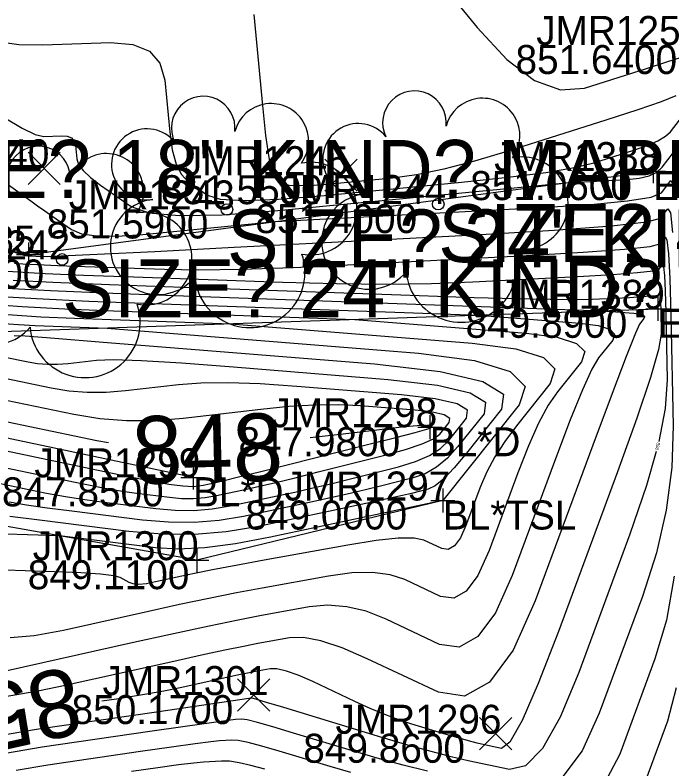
# Model space of a CAD drawing. Extents: x 1654928 to 1810050, y 486881 to 626330.
# Drawn here: x 1801531.06 to 1801558.26, y 489829.65 to 489860.85 of the extents above; entities that cross this region are included whole.
import ezdxf

# ---------------------------------------------------------------- set-up
doc = ezdxf.new("R2010")
doc.units = 0
for name, color, linetype in [('DR_X_Ditch', 7, 'Continuous'), ('DT_X_Contour_Major', 7, 'Continuous'), ('DT_X_Contour_Minor', 7, 'Continuous'), ('SV_X_Random_Point', 7, 'Continuous'), ('SV_X_Shot_Marker', 7, 'Continuous'), ('SV_X_Text_Comment', 7, 'Continuous'), ('SV_X_Text_Elevation', 7, 'Continuous'), ('SV_X_Text_Name', 7, 'Continuous'), ('SV_X_Toe_of_Slope', 7, 'Continuous'), ('SV_X_Top_of_Bank', 7, 'Continuous'), ('VG_X_Cells', 7, 'Continuous'), ('VG_X_Text', 7, 'Continuous')]:
    doc.layers.add(name, color=color, linetype=linetype)

msp = doc.modelspace()

# ---------------------------------------------------------------- linework, layer by layer
at = {"layer": 'DR_X_Ditch'}
msp.add_lwpolyline([(1801538.429, 489841.719), (1801527.515, 489844.014), (1801519.444, 489845.441), (1801503.521, 489842.761), (1801490.506, 489842.113), (1801478.561, 489839.498), (1801468.658, 489833.373), (1801465.597, 489830.762), (1801453.487, 489824.594)], dxfattribs=at)
at = {"layer": 'DT_X_Contour_Major'}
for points in [[(1801530.633, 489856.59), (1801531.351, 489856.161), (1801531.891, 489855.907), (1801532.252, 489855.829), (1801532.978, 489855.853), (1801533.218, 489855.835), (1801533.396, 489855.762), (1801533.51, 489855.634), (1801533.562, 489855.452), (1801533.615, 489854.892), (1801533.691, 489854.667), (1801533.882, 489854.412), (1801534.186, 489854.126), (1801534.603, 489853.809), (1801535.869, 489852.923), (1801536.604, 489852.664), (1801537.86, 489852.549), (1801539.637, 489852.579), (1801541.935, 489852.754), (1801553.874, 489853.908), (1801556.408, 489854.041), (1801556.905, 489854.094), (1801557.311, 489854.197), (1801557.626, 489854.35), (1801557.849, 489854.553), (1801558.322, 489855.161)], [(1801530.982, 489849.881), (1801532.625, 489849.795), (1801534.966, 489849.695), (1801538.003, 489849.583), (1801547.032, 489849.264), (1801550.067, 489849.164), (1801552.4, 489849.101), (1801554.031, 489849.075), (1801554.96, 489849.086), (1801556.503, 489849.167), (1801557.011, 489849.196), (1801557.379, 489849.224), (1801557.607, 489849.249), (1801557.695, 489849.273), (1801557.742, 489849.333), (1801557.758, 489849.306), (1801557.772, 489849.181), (1801557.783, 489848.958), (1801557.792, 489848.636), (1801557.813, 489847.648), (1801557.705, 489847.014), (1801557.367, 489845.853), (1801556.797, 489844.165), (1801555.997, 489841.951), (1801553.556, 489835.343), (1801552.722, 489833.182), (1801552.051, 489831.655), (1801551.542, 489830.76), (1801551.196, 489830.5), (1801550.491, 489830.649), (1801550.194, 489830.718), (1801549.83, 489830.813), (1801549.4, 489830.934), (1801548.904, 489831.082), (1801547.494, 489831.51), (1801546.95, 489831.689), (1801546.374, 489831.904), (1801545.767, 489832.157), (1801545.129, 489832.446), (1801543.387, 489833.265), (1801542.786, 489833.528), (1801542.293, 489833.705), (1801541.906, 489833.794), (1801541.625, 489833.797), (1801541.019, 489833.687), (1801540.749, 489833.635), (1801540.393, 489833.561), (1801539.95, 489833.466), (1801537.898, 489833.009), (1801537.224, 489832.872), (1801536.344, 489832.716), (1801535.257, 489832.541), (1801534.658, 489832.451)], [(1801530.391, 489848.098), (1801531.202, 489848.038), (1801531.898, 489848.003), (1801534.875, 489847.898), (1801547.758, 489846.856), (1801550.089, 489846.554), (1801551.561, 489846.097), (1801552.173, 489845.483), (1801551.927, 489844.714), (1801548.771, 489840.76), (1801541.633, 489839.241), (1801540.188, 489838.969), (1801538.913, 489838.805), (1801537.807, 489838.75), (1801536.871, 489838.802), (1801532.898, 489839.299), (1801529.368, 489839.415)], [(1801534.926, 489843.146), (1801534.445, 489843.224), (1801530.748, 489844.002)], [(1801530.429, 489842.872), (1801534.177, 489842.084), (1801535.434, 489841.822), (1801536.395, 489841.627), (1801537.059, 489841.499), (1801537.426, 489841.438), (1801538.01, 489841.365), (1801538.227, 489841.347), (1801538.438, 489841.345), (1801538.645, 489841.362), (1801538.847, 489841.395), (1801539.379, 489841.509), (1801539.713, 489841.586), (1801540.314, 489841.733), (1801541.183, 489841.949), (1801545.708, 489843.091), (1801546.821, 489843.374), (1801547.62, 489843.581), (1801548.105, 489843.711), (1801548.275, 489843.766), (1801548.311, 489843.81), (1801548.313, 489843.826), (1801548.292, 489843.838), (1801548.249, 489843.848), (1801548.183, 489843.856), (1801547.976, 489843.873), (1801547.71, 489843.855), (1801547.065, 489843.789), (1801546.042, 489843.675), (1801544.641, 489843.512), (1801543.284, 489843.353)]]:
    msp.add_lwpolyline(points, dxfattribs=at)
at = {"layer": 'DT_X_Contour_Minor'}
for points in [[(1801548.311, 489862.632), (1801550.187, 489860.326), (1801551.415, 489859.003), (1801552.567, 489858.145), (1801553.643, 489857.752), (1801554.643, 489857.825), (1801557.207, 489858.638), (1801558.05, 489858.907), (1801558.656, 489859.104), (1801559.025, 489859.229), (1801559.156, 489859.282), (1801559.191, 489859.326), (1801559.206, 489859.16), (1801559.225, 489858.631), (1801559.248, 489857.739), (1801559.276, 489856.483), (1801559.415, 489849.772)], [(1801558.42, 489857.501), (1801557.809, 489857.26), (1801556.841, 489856.926), (1801555.518, 489856.496), (1801551.514, 489855.226), (1801550.086, 489854.798), (1801548.807, 489854.468), (1801547.675, 489854.234), (1801546.691, 489854.097), (1801544.263, 489853.863), (1801543.451, 489853.797), (1801542.833, 489853.776), (1801542.411, 489853.8), (1801542.184, 489853.868), (1801541.839, 489854.109), (1801541.709, 489854.365), (1801541.578, 489854.949), (1801541.447, 489855.864), (1801541.314, 489857.108), (1801540.959, 489860.864)], [(1801530.348, 489859.76), (1801531.219, 489859.631), (1801532.21, 489859.611), (1801535.008, 489859.706), (1801535.936, 489859.636), (1801536.621, 489859.354), (1801537.062, 489858.862), (1801537.26, 489858.158), (1801537.464, 489856), (1801537.569, 489855.266), (1801537.73, 489854.681), (1801537.947, 489854.245), (1801538.221, 489853.959), (1801539.026, 489853.396), (1801539.556, 489853.236), (1801540.541, 489853.181), (1801541.982, 489853.23), (1801543.878, 489853.384), (1801549.542, 489853.931), (1801551.477, 489854.135), (1801553.036, 489854.337), (1801554.219, 489854.537), (1801555.026, 489854.734), (1801556.674, 489855.257), (1801557.233, 489855.452), (1801557.673, 489855.643), (1801557.993, 489855.83), (1801558.195, 489856.014), (1801558.573, 489856.499)], [(1801530.697, 489853.896), (1801531.712, 489853.159), (1801531.998, 489852.954), (1801532.291, 489852.746), (1801532.591, 489852.535), (1801533.399, 489851.97), (1801533.811, 489851.798), (1801534.442, 489851.708), (1801535.29, 489851.7), (1801536.356, 489851.773), (1801541.842, 489852.303), (1801552.822, 489852.878), (1801554.898, 489853.009), (1801556.423, 489853.156), (1801557.397, 489853.318), (1801557.818, 489853.497), (1801558.206, 489853.995), (1801558.341, 489853.775)], [(1801530.815, 489851.116), (1801531.31, 489850.941), (1801531.377, 489850.92), (1801531.428, 489850.907), (1801531.464, 489850.9), (1801531.54, 489850.892), (1801531.585, 489850.888), (1801531.663, 489850.884), (1801531.774, 489850.879), (1801531.919, 489850.874), (1801532.349, 489850.859), (1801532.957, 489850.878), (1801534.457, 489850.948), (1801536.851, 489851.068), (1801540.138, 489851.238), (1801550.094, 489851.759), (1801553.374, 489851.948), (1801555.75, 489852.125), (1801557.221, 489852.289), (1801557.787, 489852.441), (1801558.09, 489852.829), (1801558.195, 489852.658), (1801558.285, 489851.851)], [(1801544.571, 489850.497), (1801545.079, 489850.521), (1801552.23, 489850.895), (1801554.587, 489851.031), (1801556.293, 489851.158), (1801557.35, 489851.276), (1801557.756, 489851.385), (1801557.974, 489851.664), (1801558.05, 489851.541), (1801558.114, 489850.961), (1801558.167, 489849.926), (1801558.208, 489848.435), (1801558.303, 489843.852), (1801558.25, 489842.121), (1801558.022, 489840.367), (1801557.616, 489838.589), (1801557.035, 489836.789), (1801555.249, 489831.955), (1801554.536, 489830.396), (1801553.735, 489829.344)], [(1801530.537, 489850.266), (1801531.183, 489850.216), (1801532.305, 489850.158), (1801533.902, 489850.09), (1801535.975, 489850.013), (1801542.138, 489849.796), (1801544.363, 489849.735), (1801546.419, 489849.716), (1801548.304, 489849.739), (1801550.02, 489849.804), (1801554.366, 489850.031), (1801555.799, 489850.114), (1801556.836, 489850.191), (1801557.478, 489850.262), (1801557.726, 489850.329), (1801557.858, 489850.498), (1801557.904, 489850.423), (1801557.943, 489850.071), (1801557.975, 489849.442), (1801558, 489848.536), (1801558.058, 489845.75), (1801557.978, 489844.567), (1801557.711, 489843.198)], [(1801531.039, 489850.579), (1801531.384, 489850.552), (1801531.984, 489850.521), (1801532.838, 489850.485), (1801533.947, 489850.444), (1801537.243, 489850.327), (1801538.66, 489850.307), (1801540.438, 489850.332), (1801542.578, 489850.404), (1801544.152, 489850.477)], [(1801530.679, 489849.548), (1801532.536, 489849.446), (1801535.105, 489849.333), (1801538.388, 489849.21), (1801555.372, 489848.612), (1801556.675, 489848.506), (1801556.91, 489848.476), (1801557.059, 489848.429), (1801557.121, 489848.367), (1801557.096, 489848.29), (1801556.914, 489848.061), (1801556.742, 489847.684), (1801556.364, 489846.724), (1801555.778, 489845.182), (1801554.986, 489843.057), (1801552.599, 489836.614), (1801551.677, 489834.565), (1801550.701, 489833.25), (1801549.673, 489832.67), (1801548.591, 489832.824), (1801545.635, 489834.213), (1801544.603, 489834.658), (1801543.725, 489834.95), (1801543, 489835.089), (1801542.429, 489835.076), (1801541.109, 489834.837), (1801540.521, 489834.723), (1801539.746, 489834.563), (1801538.783, 489834.356), (1801537.633, 489834.102), (1801534.317, 489833.361), (1801533.134, 489833.105), (1801532.072, 489832.89), (1801531.129, 489832.716), (1801530.308, 489832.584)], [(1801530.25, 489849.221), (1801531.944, 489849.115), (1801534.116, 489849.011), (1801536.766, 489848.909), (1801550.248, 489848.433), (1801554.446, 489848.093), (1801555.205, 489847.995), (1801555.685, 489847.846), (1801555.884, 489847.646), (1801555.804, 489847.396), (1801555.216, 489846.66), (1801554.94, 489846.191), (1801554.55, 489845.339), (1801554.048, 489844.103), (1801553.432, 489842.483), (1801551.642, 489837.651), (1801550.95, 489836.114), (1801550.219, 489835.128), (1801549.447, 489834.692), (1801548.636, 489834.808), (1801546.419, 489835.85), (1801545.596, 489836.175), (1801544.791, 489836.367), (1801544.003, 489836.427), (1801543.232, 489836.355), (1801541.2, 489835.987), (1801540.294, 489835.812), (1801539.099, 489835.565), (1801537.616, 489835.246), (1801535.845, 489834.855), (1801530.737, 489833.714)], [(1801529.821, 489848.893), (1801531.352, 489848.784), (1801533.126, 489848.689), (1801535.143, 489848.607), (1801545.123, 489848.255), (1801552.216, 489847.681), (1801553.5, 489847.515), (1801554.31, 489847.263), (1801554.647, 489846.925), (1801554.512, 489846.502), (1801553.519, 489845.258), (1801553.137, 489844.699), (1801552.736, 489843.954), (1801552.317, 489843.024), (1801551.878, 489841.909), (1801550.685, 489838.687), (1801550.224, 489837.663), (1801549.736, 489837.005), (1801549.222, 489836.715), (1801548.681, 489836.792), (1801547.203, 489837.487), (1801546.589, 489837.691), (1801545.857, 489837.784), (1801545.005, 489837.765), (1801544.035, 489837.634), (1801541.29, 489837.136), (1801540.224, 489836.936), (1801539.086, 489836.709), (1801537.874, 489836.455), (1801536.589, 489836.173), (1801533.066, 489835.386), (1801531.855, 489835.16), (1801530.865, 489835.071)], [(1801530.76, 489848.453), (1801532.136, 489848.367), (1801533.521, 489848.305), (1801539.999, 489848.077), (1801549.987, 489847.268), (1801551.794, 489847.035), (1801552.936, 489846.68), (1801553.41, 489846.204), (1801553.219, 489845.608), (1801551.821, 489843.856), (1801551.334, 489843.206), (1801550.922, 489842.569), (1801550.586, 489841.945), (1801550.325, 489841.334), (1801549.728, 489839.724), (1801549.497, 489839.211), (1801549.253, 489838.883), (1801548.996, 489838.738), (1801548.726, 489838.776), (1801547.987, 489839.123), (1801547.582, 489839.208), (1801546.923, 489839.201), (1801546.008, 489839.103), (1801544.839, 489838.914), (1801541.381, 489838.286), (1801540.195, 489838.069), (1801539.231, 489837.888), (1801538.488, 489837.742), (1801537.967, 489837.633), (1801536.874, 489837.389), (1801536.498, 489837.319), (1801536.191, 489837.291), (1801535.952, 489837.306), (1801535.781, 489837.364), (1801535.417, 489837.574), (1801535.145, 489837.648), (1801534.602, 489837.713), (1801533.787, 489837.768), (1801532.7, 489837.813), (1801529.44, 489837.921)], [(1801531.029, 489847.594), (1801531.476, 489847.568), (1801532.702, 489847.475), (1801534.706, 489847.318), (1801537.488, 489847.094), (1801545.947, 489846.409), (1801548.655, 489846.099), (1801550.433, 489845.683), (1801551.283, 489845.161), (1801551.204, 489844.533), (1801549.754, 489842.717), (1801549.246, 489842.113), (1801548.811, 489841.663), (1801548.448, 489841.368), (1801548.158, 489841.226), (1801547.48, 489841.055), (1801547.1, 489840.965), (1801546.467, 489840.824), (1801545.582, 489840.632), (1801541.076, 489839.671), (1801539.797, 489839.458), (1801538.487, 489839.355), (1801537.146, 489839.362), (1801535.774, 489839.48), (1801532.074, 489839.943), (1801530.839, 489840.099)], [(1801530.582, 489846.709), (1801531.607, 489846.494), (1801531.998, 489846.429), (1801532.404, 489846.398), (1801532.823, 489846.4), (1801533.257, 489846.435), (1801534.432, 489846.573), (1801535.118, 489846.594), (1801536.292, 489846.554), (1801537.957, 489846.452), (1801540.11, 489846.289), (1801546.506, 489845.771), (1801548.553, 489845.537), (1801549.898, 489845.222), (1801550.54, 489844.828), (1801550.48, 489844.353), (1801549.384, 489842.979), (1801548.961, 489842.513), (1801548.513, 489842.143), (1801548.042, 489841.869), (1801547.545, 489841.693), (1801546.19, 489841.35), (1801545.621, 489841.211), (1801544.929, 489841.052), (1801544.115, 489840.871), (1801543.179, 489840.669), (1801540.518, 489840.102), (1801539.509, 489839.934), (1801538.474, 489839.852), (1801537.416, 489839.858), (1801536.333, 489839.951), (1801533.412, 489840.317), (1801532.394, 489840.449), (1801531.53, 489840.572), (1801530.82, 489840.687)], [(1801529.468, 489841.664), (1801531.568, 489841.223), (1801532.358, 489841.065), (1801533.151, 489840.924), (1801533.949, 489840.799), (1801534.75, 489840.69), (1801536.892, 489840.423), (1801537.686, 489840.354), (1801538.462, 489840.35), (1801539.221, 489840.41), (1801539.961, 489840.533), (1801541.912, 489840.949), (1801542.647, 489841.109), (1801543.391, 489841.279), (1801544.141, 489841.457), (1801544.9, 489841.645), (1801546.933, 489842.159), (1801547.635, 489842.371), (1801548.216, 489842.622), (1801548.676, 489842.912), (1801549.015, 489843.241), (1801549.757, 489844.172), (1801549.798, 489844.494), (1801549.363, 489844.761), (1801548.452, 489844.974), (1801547.065, 489845.133), (1801542.732, 489845.483), (1801541.208, 489845.586), (1801539.883, 489845.632), (1801538.759, 489845.621), (1801537.835, 489845.553), (1801535.638, 489845.295), (1801534.827, 489845.229), (1801534.043, 489845.226), (1801533.285, 489845.284), (1801532.553, 489845.404), (1801530.638, 489845.807)], [(1801529.948, 489842.268), (1801532.873, 489841.653), (1801533.896, 489841.444), (1801534.773, 489841.275), (1801535.504, 489841.149), (1801536.088, 489841.064), (1801537.451, 489840.894), (1801537.956, 489840.85), (1801538.45, 489840.848), (1801538.933, 489840.886), (1801539.404, 489840.964), (1801540.646, 489841.229), (1801541.18, 489841.348), (1801541.852, 489841.506), (1801542.662, 489841.703), (1801543.61, 489841.94), (1801546.32, 489842.625), (1801547.228, 489842.872), (1801547.918, 489843.101), (1801548.39, 489843.312), (1801548.645, 489843.504), (1801549.034, 489843.991), (1801549.055, 489844.16), (1801548.827, 489844.3), (1801548.35, 489844.411), (1801547.624, 489844.494), (1801545.354, 489844.678), (1801544.459, 489844.721), (1801543.474, 489844.71), (1801542.401, 489844.648), (1801541.238, 489844.532), (1801538.019, 489844.155), (1801536.831, 489844.059), (1801535.682, 489844.053), (1801534.571, 489844.138), (1801533.499, 489844.314), (1801530.693, 489844.904)], [(1801557.605, 489842.792), (1801557.207, 489841.377), (1801556.516, 489839.37), (1801554.403, 489833.649), (1801553.629, 489831.789), (1801552.893, 489830.499), (1801552.194, 489829.78), (1801551.533, 489829.63), (1801549.82, 489829.992), (1801549.115, 489830.154), (1801548.285, 489830.369), (1801547.329, 489830.637), (1801546.247, 489830.958), (1801542.192, 489832.19), (1801541.471, 489832.407), (1801541.034, 489832.536), (1801540.879, 489832.579), (1801540.843, 489832.577), (1801538.68, 489832.264), (1801537.015, 489832.022), (1801531.947, 489831.284), (1801530.234, 489831)], [(1801558.349, 489837.624), (1801558.026, 489835.802), (1801557.554, 489834.207), (1801556.096, 489830.261), (1801555.442, 489829.003)], [(1801558.436, 489833.014), (1801558.073, 489831.626), (1801556.942, 489828.567)], [(1801548.136, 489829.56), (1801547.136, 489829.805), (1801546.149, 489830.07), (1801545.175, 489830.354), (1801542.596, 489831.137), (1801541.737, 489831.393), (1801541.094, 489831.574), (1801540.667, 489831.681), (1801540.456, 489831.712), (1801540.182, 489831.696), (1801539.883, 489831.66), (1801539.192, 489831.565), (1801538.11, 489831.41), (1801536.636, 489831.197), (1801532.182, 489830.548), (1801530.662, 489830.287), (1801529.441, 489829.989), (1801528.52, 489829.655), (1801527.898, 489829.284)], [(1801544.969, 489829.502), (1801544.104, 489829.749), (1801541.998, 489830.388), (1801541.283, 489830.597), (1801540.717, 489830.742), (1801540.301, 489830.825), (1801540.034, 489830.845), (1801539.521, 489830.814), (1801539.172, 489830.778), (1801538.512, 489830.692), (1801537.54, 489830.557), (1801536.256, 489830.372), (1801532.417, 489829.813), (1801531.106, 489829.587)], [(1801541.4, 489829.64), (1801540.829, 489829.8), (1801540.341, 489829.91), (1801539.935, 489829.969), (1801539.611, 489829.978), (1801538.86, 489829.933), (1801538.462, 489829.896), (1801537.832, 489829.819), (1801536.97, 489829.703), (1801535.877, 489829.547)]]:
    msp.add_lwpolyline(points, dxfattribs=at)
at = {"layer": 'SV_X_Random_Point'}
for p, q in [((1801531.601, 489853.837), (1801532.934, 489855.172)), ((1801531.601, 489855.172), (1801532.934, 489853.837)), ((1801543.886, 489853.554), (1801545.219, 489854.889)), ((1801543.886, 489854.889), (1801545.219, 489853.554)), ((1801540.276, 489832.042), (1801541.609, 489833.377)), ((1801540.276, 489833.377), (1801541.609, 489832.042)), ((1801550.294, 489830.441), (1801551.627, 489831.776)), ((1801550.294, 489831.776), (1801551.627, 489830.441))]:
    msp.add_line(p, q, dxfattribs=at)
at = {"layer": 'SV_X_Shot_Marker'}
for p, q in [((1801557.484, 489854.89), (1801557.484, 489853.89)), ((1801556.984, 489854.39), (1801557.984, 489854.39)), ((1801557.484, 489854.39), (1801557.484, 489854.39)), ((1801531.615, 489851.439), (1801531.615, 489850.439)), ((1801531.115, 489850.939), (1801532.115, 489850.939)), ((1801531.615, 489850.939), (1801531.615, 489850.939)), ((1801557.678, 489849.192), (1801557.678, 489848.192)), ((1801557.178, 489848.692), (1801558.178, 489848.692)), ((1801557.678, 489848.692), (1801557.678, 489848.692)), ((1801548.238, 489844.292), (1801548.238, 489843.292)), ((1801547.738, 489843.792), (1801548.738, 489843.792)), ((1801548.238, 489843.792), (1801548.238, 489843.792)), ((1801538.429, 489842.219), (1801538.429, 489841.219)), ((1801537.929, 489841.719), (1801538.929, 489841.719)), ((1801538.429, 489841.719), (1801538.429, 489841.719)), ((1801548.771, 489841.26), (1801548.771, 489840.26)), ((1801548.271, 489840.76), (1801549.271, 489840.76)), ((1801548.771, 489840.76), (1801548.771, 489840.76)), ((1801538.587, 489838.79), (1801538.587, 489837.79)), ((1801538.087, 489838.29), (1801539.087, 489838.29)), ((1801538.587, 489838.29), (1801538.587, 489838.29))]:
    msp.add_line(p, q, dxfattribs=at)
at = {"layer": 'SV_X_Toe_of_Slope'}
for points in [[(1801453.22, 489833.952), (1801462.62, 489833.764), (1801469.81, 489840.55), (1801480.323, 489844.16), (1801485.248, 489845.996), (1801491.16, 489848.502), (1801498.28, 489846.461), (1801505.556, 489847.392), (1801507.978, 489849.684), (1801520.732, 489849.249), (1801530.519, 489847.747), (1801557.678, 489848.692)], [(1801548.771, 489840.76), (1801538.587, 489838.29), (1801528.242, 489840.124), (1801519.185, 489843.217), (1801514.834, 489840.706), (1801503.746, 489839.863), (1801493.235, 489835.949), (1801481.982, 489831.828), (1801478.469, 489833.99), (1801472.566, 489830.006), (1801464.849, 489824.991), (1801462.27, 489825.427), (1801460.621, 489820.525)]]:
    msp.add_lwpolyline(points, dxfattribs=at)
at = {"layer": 'SV_X_Top_of_Bank'}
msp.add_lwpolyline([(1801452.193, 489836.758), (1801459.513, 489846.009), (1801465.887, 489850.179), (1801473.853, 489849.345), (1801479.986, 489850.885), (1801482.71, 489854.488), (1801486.035, 489852.905), (1801488.583, 489850.107), (1801492.084, 489852.448), (1801498.522, 489852.672), (1801506.396, 489853.841), (1801518.285, 489853.998), (1801520.681, 489853.368), (1801531.615, 489850.939), (1801557.484, 489854.39)], dxfattribs=at)
at = {"layer": 'VG_X_Cells'}
for centre in [(1801539.835, 489852.803), (1801548.581, 489853.025), (1801533.011, 489850.735)]:
    msp.add_circle(centre, 0.24, dxfattribs=at)
for centre, radius, start, end in [((1801547.597, 489856.392), 1.317, 354.0047, 205.9741), ((1801538.851, 489856.171), 1.317, 354.0047, 205.9741), ((1801550.407, 489855.854), 1.553, 323.83, 165.0376), ((1801541.661, 489855.632), 1.553, 323.83, 165.0376), ((1801536.525, 489854.667), 1.471, 39.0625, 279.5412), ((1801545.272, 489854.889), 1.471, 39.0625, 279.5412), ((1801532.027, 489854.102), 1.317, 354.0047, 205.9741), ((1801534.837, 489853.564), 1.553, 323.83, 165.0376), ((1801552.041, 489853.061), 1.915, 259.1453, 101.4596), ((1801543.295, 489852.839), 1.915, 259.1453, 101.4596), ((1801545.728, 489851.476), 1.974, 96.1722, 320.5737), ((1801536.981, 489851.255), 1.974, 96.1722, 320.5737), ((1801536.471, 489850.771), 1.915, 259.1453, 101.4596), ((1801530.158, 489849.186), 1.974, 96.1722, 320.5737), ((1801549.528, 489850.42), 2.284, 184.9476, 19.4572), ((1801540.781, 489850.198), 2.284, 184.9476, 19.4572), ((1801533.958, 489848.129), 2.284, 184.9476, 19.4572)]:
    msp.add_arc(centre, radius, start, end, dxfattribs=at)

# ---------------------------------------------------------------- texts
at = {"layer": 'DT_X_Contour_Major'}
for s, rotation, p in [('848', 1.4202, (1801535.936, 489841.431)), ('850', 192.5187, (1801533.427, 489833.927))]:
    msp.add_text(s, height=2.8, rotation=rotation, dxfattribs=at).set_placement(p)
at = {"layer": 'DT_X_Contour_Minor'}
for rotation, p in [(2.6857, (1801544.199, 489850.41)), (255.2981, (1801557.636, 489843.172))]:
    msp.add_text('850', height=0.14, rotation=rotation, dxfattribs=at).set_placement(p)
at = {"layer": 'SV_X_Text_Comment'}
for s, p in [('EL*TB', (1801557.484, 489853.19)), ('EL*TSL', (1801557.678, 489847.492)), ('BL*D', (1801548.238, 489842.592)), ('BL*D', (1801538.429, 489840.519)), ('BL*TSL', (1801548.771, 489839.56))]:
    msp.add_text(s, height=1.2, dxfattribs=at).set_placement(p)
at = {"layer": 'SV_X_Text_Elevation'}
for s, p in [('851.6400', (1801551.78, 489858.408)), ('851.5500', (1801537.108, 489853.022)), ('851.0600', (1801549.907, 489853.19)), ('851.4000', (1801541.014, 489851.825)), ('851.5900', (1801532.371, 489851.603)), ('851.2400', (1801525.576, 489849.535)), ('849.8900', (1801549.713, 489847.492)), ('847.9800', (1801540.311, 489842.592)), ('847.8500', (1801530.521, 489840.519)), ('849.0000', (1801540.598, 489839.56)), ('849.1100', (1801531.587, 489837.09)), ('850.1700', (1801533.403, 489831.509)), ('849.8600', (1801542.996, 489829.908))]:
    msp.add_text(s, height=1.2, dxfattribs=at).set_placement(p)
at = {"layer": 'SV_X_Text_Name'}
for s, p in [('JMR1256', (1801552.639, 489859.608)), ('JMR1240', (1801525.616, 489854.505)), ('JMR1388', (1801550.899, 489854.39)), ('JMR1245', (1801538.005, 489854.222)), ('JMR1244', (1801542.044, 489853.025)), ('JMR1243', (1801533.288, 489852.803)), ('JMR1385', (1801525.039, 489850.939)), ('JMR1242', (1801526.474, 489850.735)), ('JMR1389', (1801551.093, 489848.692)), ('JMR1298', (1801541.672, 489843.792)), ('JMR1299', (1801531.863, 489841.719)), ('JMR1297', (1801542.214, 489840.76)), ('JMR1300', (1801531.795, 489838.29)), ('JMR1301', (1801534.687, 489832.709)), ('JMR1296', (1801544.329, 489831.108))]:
    msp.add_text(s, height=1.2, dxfattribs=at).set_placement(p)
at = {"layer": 'VG_X_Text'}
for s, p in [('SIZE? 18" KIND? MAPLE', (1801525.28, 489853.28)), ('SIZE? 48" KIND? MAPLE', (1801548.581, 489850.625)), ('SIZE? 24" KIND? MAPLE', (1801539.835, 489850.403)), ('SIZE? 24" KIND? MAPLE', (1801533.011, 489848.335))]:
    msp.add_text(s, height=2.4, dxfattribs=at).set_placement(p)

doc.saveas('drawing.dxf')
